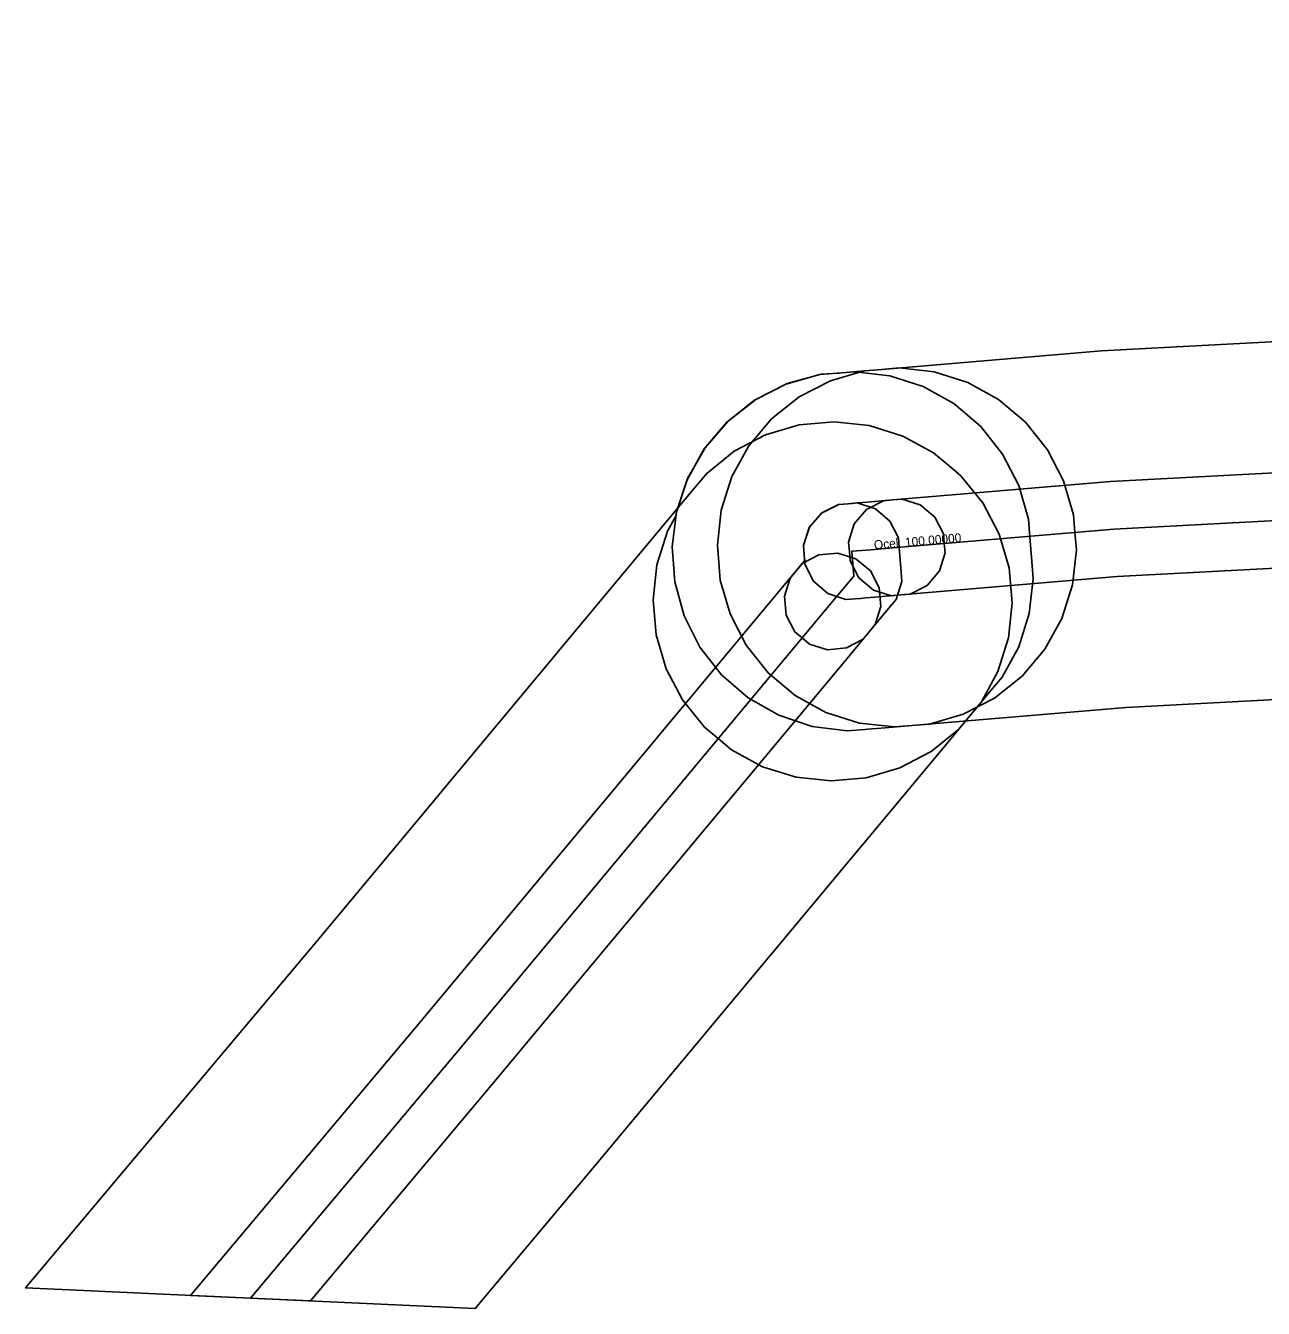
# Model space of a CAD drawing. Extents: x -574809 to -573797, y -1188298 to -1187412.
# Drawn here: x -574809.3 to -574705.3, y -1188298.1 to -1188190.4 of the extents above; entities that cross this region are included whole.
import ezdxf

# ---------------------------------------------------------------- set-up
doc = ezdxf.new("R2010")
doc.units = 0
for name, color, linetype in [('Vrstva 1', 7, 'Continuous'), ('Vrstva 34', 7, 'Continuous'), ('Vrstva 40', 7, 'Continuous')]:
    doc.layers.add(name, color=color, linetype=linetype)

msp = doc.modelspace()

# ---------------------------------------------------------------- linework, layer by layer
at = {"layer": 'Vrstva 1'}
for points in [[(-574690.168, -1188246.21), (-574716.871, -1188247.617), (-574734.843, -1188249.141), (-574736.315, -1188249.266), (-574739.251, -1188248.936), (-574742.067, -1188248.041), (-574744.654, -1188246.613), (-574746.912, -1188244.707), (-574748.755, -1188242.398), (-574750.113, -1188239.774), (-574750.932, -1188236.935), (-574751.057, -1188235.463), (-574751.182, -1188233.991), (-574750.852, -1188231.055), (-574749.957, -1188228.239), (-574748.529, -1188225.652), (-574746.623, -1188223.394), (-574744.314, -1188221.551), (-574741.69, -1188220.193), (-574738.851, -1188219.374), (-574737.379, -1188219.249), (-574718.929, -1188217.683), (-574690.952, -1188216.21)], [(-574690.455, -1188235.21), (-574717.626, -1188236.641), (-574735.773, -1188238.181), (-574736.566, -1188238.248), (-574738.082, -1188237.766), (-574739.299, -1188236.739), (-574740.03, -1188235.326), (-574740.097, -1188234.533), (-574740.164, -1188233.74), (-574739.682, -1188232.224), (-574738.655, -1188231.007), (-574737.242, -1188230.276), (-574736.449, -1188230.209), (-574718.174, -1188228.659), (-574690.665, -1188227.21)]]:
    msp.add_lwpolyline(points, dxfattribs=at)
for points in [[(-574756.259, -1188235.655), (-574755.377, -1188232.835), (-574754.653, -1188231.508), (-574754.631, -1188231.318), (-574753.725, -1188228.506), (-574752.288, -1188225.924), (-574750.375, -1188223.672), (-574748.06, -1188221.837), (-574745.43, -1188220.488), (-574742.589, -1188219.679), (-574741.116, -1188219.559), (-574739.643, -1188219.439), (-574736.708, -1188219.779), (-574733.896, -1188220.685), (-574731.314, -1188222.122), (-574729.062, -1188224.035), (-574727.227, -1188226.35), (-574725.878, -1188228.98), (-574725.069, -1188231.821), (-574724.949, -1188233.294), (-574724.779, -1188235.384), (-574724.661, -1188236.84), (-574724.991, -1188239.744), (-574725.875, -1188242.53), (-574727.28, -1188245.092), (-574728.216, -1188246.214), (-574729.987, -1188248.335), (-574730.934, -1188249.469), (-574733.234, -1188251.324), (-574735.851, -1188252.695), (-574738.686, -1188253.528), (-574741.629, -1188253.793), (-574744.567, -1188253.479), (-574747.387, -1188252.597), (-574749.981, -1188251.182), (-574751.115, -1188250.235), (-574752.249, -1188249.288), (-574754.104, -1188246.988), (-574755.475, -1188244.371), (-574756.308, -1188241.536), (-574756.573, -1188238.593)], [(-574745.317, -1188220.444), (-574742.468, -1188219.658), (-574740.995, -1188219.55), (-574740.749, -1188219.532), (-574740.356, -1188219.495), (-574739.5, -1188219.429), (-574737.38, -1188219.249), (-574735.908, -1188219.124), (-574732.972, -1188219.453), (-574730.156, -1188220.349), (-574727.569, -1188221.777), (-574725.311, -1188223.682), (-574723.467, -1188225.991), (-574722.11, -1188228.615), (-574721.29, -1188231.454), (-574721.165, -1188232.926), (-574721.04, -1188234.398), (-574721.369, -1188237.334), (-574722.265, -1188240.15), (-574723.693, -1188242.737), (-574725.598, -1188244.995), (-574727.907, -1188246.839), (-574730.531, -1188248.196), (-574733.37, -1188249.016), (-574734.842, -1188249.141), (-574737.08, -1188249.331), (-574737.784, -1188249.385), (-574738.231, -1188249.428), (-574738.805, -1188249.47), (-574740.278, -1188249.578), (-574743.211, -1188249.214), (-574746.016, -1188248.286), (-574748.586, -1188246.828), (-574750.822, -1188244.897), (-574752.639, -1188242.567), (-574753.966, -1188239.927), (-574754.752, -1188237.078), (-574754.86, -1188235.605), (-574754.968, -1188234.132), (-574754.604, -1188231.199), (-574753.676, -1188228.394), (-574752.218, -1188225.824), (-574750.287, -1188223.588), (-574747.957, -1188221.771)], [(-574761.456, -1188286.096), (-574771.515, -1188298.069), (-574809.256, -1188296.355), (-574784.464, -1188266.844), (-574754.739, -1188231.172), (-574753.016, -1188229.108), (-574752.069, -1188227.974), (-574749.769, -1188226.119), (-574747.152, -1188224.748), (-574744.317, -1188223.914), (-574741.374, -1188223.649), (-574738.436, -1188223.963), (-574735.616, -1188224.845), (-574733.022, -1188226.259), (-574731.888, -1188227.206), (-574730.754, -1188228.153), (-574728.899, -1188230.453), (-574727.528, -1188233.07), (-574726.694, -1188235.905), (-574726.429, -1188238.848), (-574726.743, -1188241.786), (-574727.625, -1188244.606), (-574729.039, -1188247.2), (-574729.986, -1188248.334), (-574731.701, -1188250.388)], [(-574742.407, -1188231.294), (-574740.985, -1188230.579), (-574740.192, -1188230.521), (-574739.826, -1188230.494), (-574739.413, -1188230.455), (-574738.613, -1188230.393), (-574736.449, -1188230.209), (-574735.656, -1188230.142), (-574734.14, -1188230.624), (-574732.924, -1188231.651), (-574732.192, -1188233.064), (-574732.125, -1188233.857), (-574732.058, -1188234.65), (-574732.54, -1188236.166), (-574733.567, -1188237.382), (-574734.98, -1188238.114), (-574735.773, -1188238.181), (-574737.967, -1188238.367), (-574738.727, -1188238.425), (-574739.154, -1188238.466), (-574739.608, -1188238.499), (-574740.401, -1188238.557), (-574741.912, -1188238.057), (-574743.116, -1188237.017), (-574743.831, -1188235.595), (-574743.889, -1188234.802), (-574743.947, -1188234.009), (-574743.447, -1188232.498)], [(-574745.556, -1188238.287), (-574745.081, -1188236.768), (-574744.571, -1188236.157), (-574743.85, -1188235.293), (-574743.887, -1188234.834), (-574743.951, -1188234.041), (-574743.464, -1188232.526), (-574742.433, -1188231.314), (-574741.017, -1188230.587), (-574740.224, -1188230.523), (-574739.431, -1188230.459), (-574737.916, -1188230.946), (-574736.704, -1188231.977), (-574735.977, -1188233.393), (-574735.913, -1188234.186), (-574735.743, -1188236.276), (-574735.679, -1188237.06), (-574736.155, -1188238.56), (-574736.66, -1188239.164), (-574738.431, -1188241.285), (-574738.941, -1188241.896), (-574740.35, -1188242.634), (-574741.935, -1188242.776), (-574743.454, -1188242.301), (-574744.065, -1188241.791), (-574744.676, -1188241.281), (-574745.414, -1188239.872)], [(-574769.892, -1188279.037), (-574785.354, -1188297.441), (-574795.418, -1188296.983), (-574776.028, -1188273.903), (-574746.292, -1188238.218), (-574744.572, -1188236.157), (-574744.062, -1188235.546), (-574742.652, -1188234.808), (-574741.067, -1188234.666), (-574739.548, -1188235.14), (-574738.937, -1188235.65), (-574738.326, -1188236.16), (-574737.588, -1188237.57), (-574737.446, -1188239.155), (-574737.92, -1188240.674), (-574738.43, -1188241.285), (-574740.148, -1188243.342)]]:
    msp.add_lwpolyline(points, close=True, dxfattribs=at)
at = {"layer": 'Vrstva 34'}
msp.add_line((-574743.22, -1188240.78), (-574741.501, -1188238.721), dxfattribs=at)
for points in [[(-574736.111, -1188234.195), (-574717.9, -1188232.65), (-574690.56, -1188231.21), (-574659.41, -1188231.22), (-574646.03, -1188229.47), (-574634.82, -1188226.94), (-574620.99, -1188223.55), (-574607.13, -1188220.14), (-574599.65, -1188218.11), (-574584.12, -1188213.6), (-574568.2, -1188209.54), (-574543.13, -1188203.59), (-574531.48, -1188199.5), (-574521.61, -1188192.29), (-574519.6, -1188190.39)], [(-574741.501, -1188238.721), (-574739.73, -1188236.6), (-574739.9, -1188234.51)], [(-574739.9, -1188234.51), (-574739.49, -1188234.48), (-574739.07, -1188234.44), (-574738.29, -1188234.38), (-574736.111, -1188234.195)], [(-574790.386, -1188297.212), (-574772.96, -1188276.47), (-574743.22, -1188240.78)]]:
    msp.add_lwpolyline(points, dxfattribs=at)

# ---------------------------------------------------------------- texts
at = {"layer": 'Vrstva 40'}
msp.add_text('Ocel  100.00000', height=0.75, rotation=4.85295, dxfattribs=at).set_placement((-574738.005, -1188234.356))

doc.saveas('drawing.dxf')
